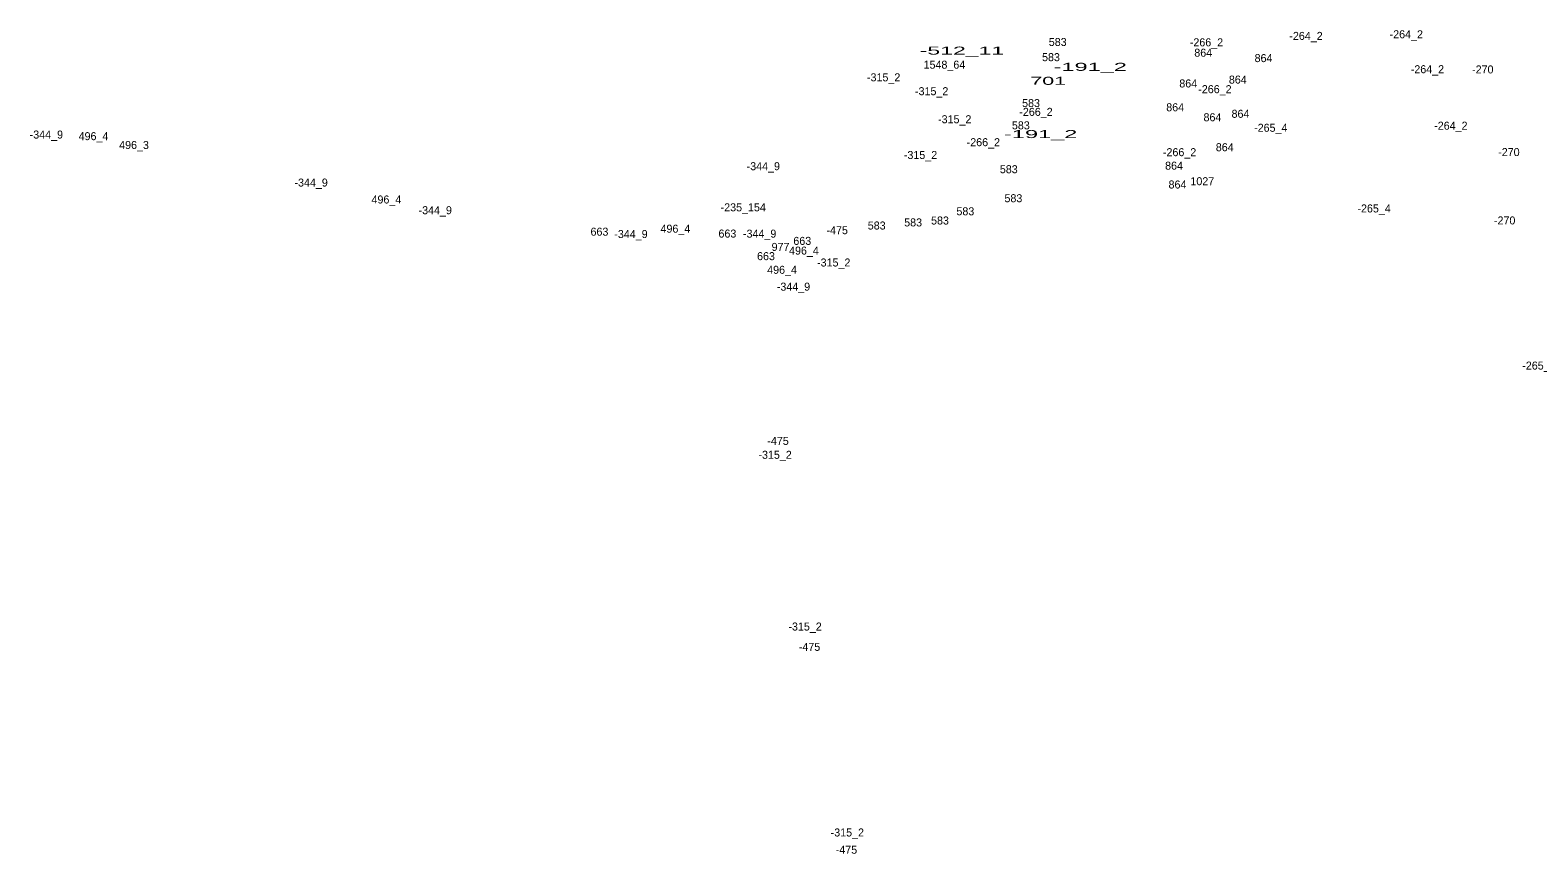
# Model space of a CAD drawing. Extents: x -660434 to -656144, y -997850 to -994016.
# Drawn here: x -658885 to -658131, y -997194 to -996782 of the extents above; entities that cross this region are included whole.
import ezdxf
from ezdxf.enums import TextEntityAlignment as Align

# ---------------------------------------------------------------- set-up
doc = ezdxf.new("R2010")
doc.units = 0
doc.header["$LTSCALE"] = 1.6
doc.layers.add('24', color=7, linetype='Continuous')

msp = doc.modelspace()

# ---------------------------------------------------------------- texts
at = {"layer": '24'}
for s, p in [('-264_2', (-658247.242, -996786.98)), ('-264_2', (-658197.122, -996786.16)), ('583', (-658371.347, -996790.01)), ('-266_2', (-658296.993, -996790.18)), ('864', (-658298.617, -996795.38)), ('1548_64', (-658427.972, -996801.36)), ('583', (-658374.707, -996797.6)), ('864', (-658268.477, -996798.07)), ('-264_2', (-658186.562, -996803.63)), ('-270', (-658158.894, -996803.75)), ('-315_2', (-658458.346, -996807.68)), ('864', (-658306.107, -996810.75)), ('864', (-658281.337, -996808.82)), ('-315_2', (-658434.346, -996814.62)), ('-266_2', (-658292.773, -996813.61)), ('-266_2', (-658382.203, -996824.94)), ('583', (-658384.687, -996820.55)), ('864', (-658312.637, -996822.65)), ('864', (-658279.997, -996825.92)), ('-315_2', (-658422.826, -996828.64)), ('583', (-658389.777, -996831.69)), ('864', (-658294.007, -996827.65)), ('-265_4', (-658264.862, -996832.9)), ('-264_2', (-658174.852, -996831.87)), ('-344_9', (-658876.836, -996836.3)), ('496_4', (-658853.264, -996837.1)), ('496_3', (-658833.01, -996841.52)), ('-266_2', (-658408.513, -996840.12)), ('-315_2', (-658439.916, -996846.5)), ('-266_2', (-658310.433, -996845.11)), ('864', (-658287.867, -996842.63)), ('-270', (-658145.834, -996845.05)), ('-344_9', (-658518.486, -996852.12)), ('583', (-658395.807, -996853.62)), ('864', (-658313.207, -996851.85)), ('-344_9', (-658744.486, -996860.29)), ('864', (-658311.487, -996861.26)), ('1027', (-658299.08, -996859.62)), ('496_4', (-658706.874, -996868.75)), ('583', (-658393.497, -996868.12)), ('-344_9', (-658682.466, -996874.12)), ('-235_154', (-658528.519, -996872.67)), ('583', (-658430.177, -996879.26)), ('583', (-658417.507, -996874.65)), ('-265_4', (-658213.212, -996873.23)), ('-270', (-658147.954, -996879.22)), ('663', (-658600.388, -996884.84)), ('-344_9', (-658584.636, -996886.03)), ('496_4', (-658562.434, -996883.35)), ('663', (-658536.448, -996885.8)), ('-344_9', (-658520.316, -996885.83)), ('-475', (-658481.555, -996884.11)), ('583', (-658461.817, -996881.76)), ('583', (-658443.617, -996880.22)), ('977', (-658509.893, -996892.47)), ('496_4', (-658498.184, -996894.3)), ('663', (-658499.008, -996889.45)), ('663', (-658517.148, -996897.08)), ('-315_2', (-658483.306, -996900.25)), ('496_4', (-658509.124, -996903.9)), ('-344_9', (-658503.416, -996912.34)), ('-265_4', (-658130.832, -996951.79)), ('-475', (-658511.125, -996989.45)), ('-315_2', (-658512.596, -996996.38)), ('-315_2', (-658497.616, -997082.24)), ('-475', (-658495.375, -997092.4)), ('-315_2', (-658476.496, -997185.19)), ('-475', (-658476.945, -997193.82))]:
    msp.add_text(s, height=4, dxfattribs=at).set_placement(p, align=Align.CENTER)
for s, width, p in [('-512_11', 2.15, (-658419.214, -996794.33)), ('-191_2', 2.2, (-658355.083, -996802.44)), ('701', 2, (-658376.099, -996809.43)), ('-191_2', 2.2, (-658379.853, -996836.05))]:
    msp.add_text(s, height=4, dxfattribs=dict(at, width=width)).set_placement(p, align=Align.CENTER)

doc.saveas('drawing.dxf')
